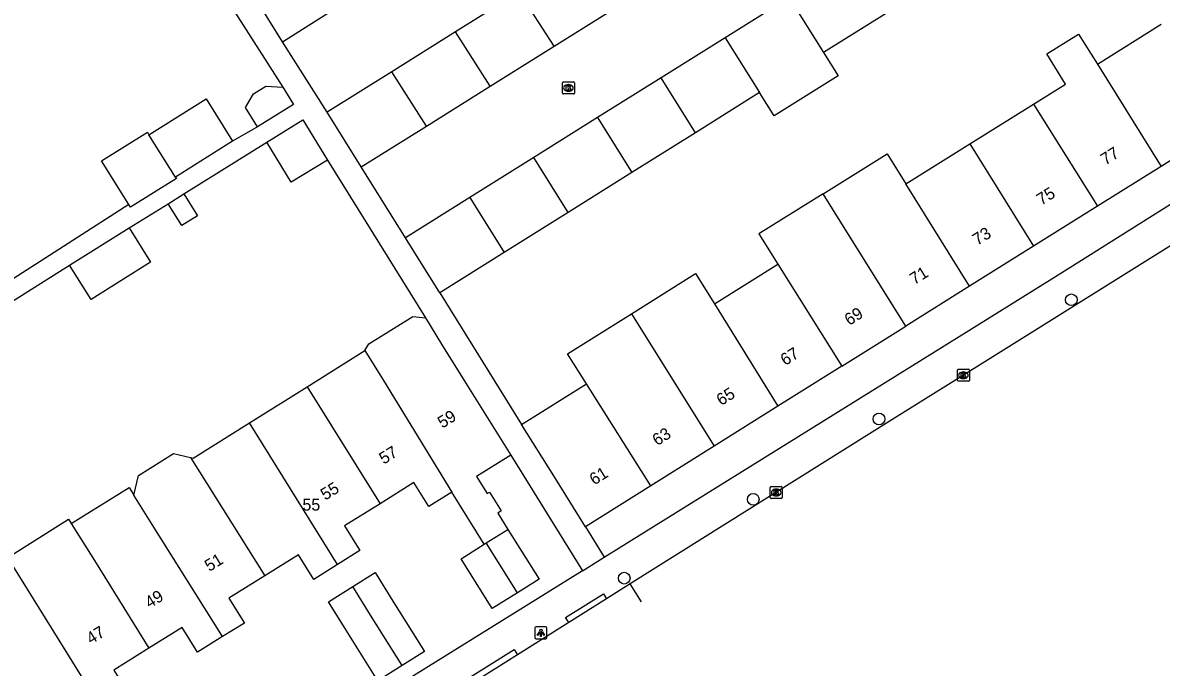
# Model space of a CAD drawing. Extents: x 157767 to 159171, y 387842 to 389425.
# Drawn here: x 158500 to 158595.3, y 387925 to 387978.8 of the extents above; entities that cross this region are included whole.
import ezdxf

# ---------------------------------------------------------------- set-up
doc = ezdxf.new("R2010")
doc.units = 0
for name, color, linetype in [('IMGEO_Boom', 7, 'Continuous'), ('IMGEO_Kolk', 7, 'Continuous'), ('IMGEO_Lichtpunt', 7, 'Continuous'), ('IMGEO_Pand', 7, 'Continuous'), ('IMGEO_Pand_nummerreeks', 7, 'Continuous'), ('IMGEO_Rijbaan_lokaal_gesloten', 7, 'Continuous'), ('IMGEO_Rijbaan_lokaal_open', 7, 'Continuous'), ('IMGEO_Voetpad_open', 7, 'Continuous')]:
    doc.layers.add(name, color=color, linetype=linetype)

msp = doc.modelspace()

# ---------------------------------------------------------------- linework, layer by layer
at = {"layer": 'IMGEO_Boom'}
for centre in [(158587.737, 387955.672), (158571.642, 387945.71), (158561.12, 387938.99), (158550.326, 387932.404)]:
    msp.add_circle(centre, 0.489, dxfattribs=at)
at = {"layer": 'IMGEO_Kolk'}
for p, q in [((158545.159, 387972.955), (158545.159, 387973.807)), ((158545.234, 387973.881), (158546.086, 387973.881)), ((158545.647, 387973.661), (158545.672, 387973.661)), ((158546.16, 387973.807), (158546.16, 387972.955)), ((158546.086, 387972.881), (158545.234, 387972.881)), ((158545.67, 387973.101), (158545.645, 387973.101)), ((158578.205, 387948.94), (158578.205, 387949.792)), ((158578.28, 387949.866), (158579.132, 387949.866)), ((158578.693, 387949.646), (158578.718, 387949.646)), ((158579.206, 387949.792), (158579.206, 387948.94)), ((158579.132, 387948.866), (158578.28, 387948.866)), ((158578.716, 387949.086), (158578.691, 387949.086)), ((158562.544, 387939.138), (158562.544, 387939.99)), ((158562.619, 387940.064), (158563.471, 387940.064)), ((158563.032, 387939.844), (158563.057, 387939.844)), ((158563.545, 387939.99), (158563.545, 387939.138)), ((158563.471, 387939.064), (158562.619, 387939.064)), ((158563.055, 387939.284), (158563.03, 387939.284))]:
    msp.add_line(p, q, dxfattribs=at)
for points in [[(158545.159, 387972.955), (158545.159, 387973.807)], [(158545.234, 387973.881), (158546.086, 387973.881)], [(158545.48, 387973.581), (158545.603, 387973.581), (158545.603, 387973.43), (158545.733, 387973.581), (158545.897, 387973.581), (158545.751, 387973.43), (158545.904, 387973.181), (158545.752, 387973.181), (158545.667, 387973.345), (158545.603, 387973.278), (158545.603, 387973.181), (158545.48, 387973.181), (158545.48, 387973.581)], [(158546.16, 387973.807), (158546.16, 387972.955)], [(158546.086, 387972.881), (158545.234, 387972.881)], [(158578.205, 387948.94), (158578.205, 387949.792)], [(158578.28, 387949.866), (158579.132, 387949.866)], [(158578.526, 387949.566), (158578.649, 387949.566), (158578.649, 387949.415), (158578.779, 387949.566), (158578.943, 387949.566), (158578.797, 387949.415), (158578.95, 387949.166), (158578.798, 387949.166), (158578.713, 387949.33), (158578.649, 387949.263), (158578.649, 387949.166), (158578.526, 387949.166), (158578.526, 387949.566)], [(158579.206, 387949.792), (158579.206, 387948.94)], [(158579.132, 387948.866), (158578.28, 387948.866)], [(158562.544, 387939.138), (158562.544, 387939.99)], [(158562.619, 387940.064), (158563.471, 387940.064)], [(158563.545, 387939.99), (158563.545, 387939.138)], [(158563.471, 387939.064), (158562.619, 387939.064)], [(158562.865, 387939.764), (158562.988, 387939.764), (158562.988, 387939.613), (158563.118, 387939.764), (158563.282, 387939.764), (158563.136, 387939.613), (158563.289, 387939.364), (158563.137, 387939.364), (158563.052, 387939.528), (158562.988, 387939.461), (158562.988, 387939.364), (158562.865, 387939.364), (158562.865, 387939.764)]]:
    msp.add_lwpolyline(points, dxfattribs=at)
for centre, start, end in [((158545.236, 387973.805), 91.55205, 178.44795), ((158545.236, 387973.805), 91.55205, 178.44795), ((158546.084, 387973.805), 1.55205, 88.44795), ((158546.084, 387973.805), 1.55205, 88.44795), ((158545.236, 387972.957), 181.55205, 268.44795), ((158545.236, 387972.957), 181.55205, 268.44795), ((158546.084, 387972.957), 271.55205, 358.44795), ((158546.084, 387972.957), 271.55205, 358.44795), ((158578.282, 387949.79), 91.55205, 178.44795), ((158578.282, 387949.79), 91.55205, 178.44795), ((158579.13, 387949.79), 1.55205, 88.44795), ((158579.13, 387949.79), 1.55205, 88.44795), ((158578.282, 387948.942), 181.55205, 268.44795), ((158578.282, 387948.942), 181.55205, 268.44795), ((158579.13, 387948.942), 271.55205, 358.44795), ((158579.13, 387948.942), 271.55205, 358.44795), ((158562.621, 387939.988), 91.55205, 178.44795), ((158562.621, 387939.988), 91.55205, 178.44795), ((158563.469, 387939.988), 1.55205, 88.44795), ((158563.469, 387939.988), 1.55205, 88.44795), ((158562.621, 387939.14), 181.55205, 268.44795), ((158562.621, 387939.14), 181.55205, 268.44795), ((158563.469, 387939.14), 271.55205, 358.44795), ((158563.469, 387939.14), 271.55205, 358.44795)]:
    msp.add_arc(centre, 0.0765, start, end, dxfattribs=at)
for centre, major_axis, ratio, start_param, end_param in [((158545.646, 387973.381), (-0.387, 0.002), 0.722429, 4.712389, 7.853982), ((158545.671, 387973.381), (-0.39, 0.002), 0.717154, 1.570796, 4.712389), ((158578.692, 387949.366), (-0.387, 0.002), 0.722429, 4.712389, 7.853982), ((158578.717, 387949.366), (-0.39, 0.002), 0.717154, 1.570796, 4.712389), ((158563.031, 387939.564), (-0.387, 0.002), 0.722429, 4.712389, 7.853982), ((158563.056, 387939.564), (-0.39, 0.002), 0.717154, 1.570796, 4.712389)]:
    msp.add_ellipse(centre, major_axis=major_axis, ratio=ratio, start_param=start_param, end_param=end_param, dxfattribs=at)
at = {"layer": 'IMGEO_Lichtpunt'}
for p, q in [((158542.853, 387928.241), (158542.853, 387927.434)), ((158542.853, 387928.241), (158542.853, 387927.434)), ((158543.755, 387928.336), (158542.947, 387928.336)), ((158543.755, 387928.336), (158542.947, 387928.336)), ((158543.849, 387927.434), (158543.849, 387928.241)), ((158543.849, 387927.434), (158543.849, 387928.241)), ((158542.947, 387927.34), (158543.755, 387927.34)), ((158542.947, 387927.34), (158543.755, 387927.34))]:
    msp.add_line(p, q, dxfattribs=at)
for points in [[(158543.227, 387927.905), (158543.266, 387927.877), (158543.078, 387927.615), (158543.04, 387927.642), (158543.227, 387927.905)], [(158543.329, 387927.857), (158543.376, 387927.857), (158543.376, 387927.535), (158543.329, 387927.535), (158543.329, 387927.857)], [(158543.439, 387927.877), (158543.477, 387927.904), (158543.664, 387927.642), (158543.625, 387927.614), (158543.439, 387927.877)]]:
    msp.add_lwpolyline(points, dxfattribs=at)
msp.add_circle((158543.352, 387928.039), 0.0994, dxfattribs=at)
for centre, start, end in [((158542.947, 387928.241), 90, 180), ((158542.947, 387928.241), 90, 180), ((158542.947, 387927.434), 180, 270), ((158542.947, 387927.434), 180, 270), ((158543.755, 387928.241), 0, 90), ((158543.755, 387928.241), 0, 90), ((158543.755, 387927.434), 270, 0), ((158543.755, 387927.434), 270, 360)]:
    msp.add_arc(centre, 0.0946, start, end, dxfattribs=at)
at = {"layer": 'IMGEO_Pand'}
for points in [[(158521.74, 387977.25), (158519.437, 387980.934), (158516.702, 387985.309), (158514.051, 387989.548)], [(158521.74, 387977.25), (158527.213, 387980.683), (158524.909, 387984.355)], [(158541.544, 387981.403), (158536.208, 387978.066)], [(158544.463, 387976.874), (158541.544, 387981.403)], [(158564.131, 387980.929), (158558.764, 387977.574)], [(158564.131, 387980.929), (158567.009, 387976.336)], [(158544.463, 387976.874), (158549.81, 387980.217)], [(158572.341, 387979.67), (158567.009, 387976.336)], [(158536.208, 387978.066), (158530.877, 387974.733)], [(158539.11, 387973.527), (158536.208, 387978.066)], [(158589.921, 387975.378), (158595.269, 387978.721)], [(158558.764, 387977.574), (158553.428, 387974.237)], [(158558.764, 387977.574), (158561.653, 387972.988)], [(158584.581, 387972.039), (158587.251, 387973.708), (158585.68, 387976.221), (158588.347, 387977.888), (158589.921, 387975.378)], [(158539.11, 387973.527), (158544.463, 387976.874)], [(158567.009, 387976.336), (158568.227, 387974.393), (158562.879, 387971.042), (158561.653, 387972.988)], [(158589.921, 387975.378), (158595.252, 387966.827)], [(158530.877, 387974.733), (158525.46, 387971.346)], [(158533.781, 387970.195), (158530.877, 387974.733)], [(158553.428, 387974.237), (158548.092, 387970.901)], [(158556.304, 387969.643), (158553.428, 387974.237)], [(158519.639, 387970.118), (158518.623, 387971.743), (158519.308, 387972.886), (158520.336, 387973.529), (158521.756, 387973.455)], [(158521.756, 387973.455), (158522.661, 387972.008), (158519.639, 387970.118)], [(158533.781, 387970.195), (158539.11, 387973.527)], [(158510.561, 387969.468), (158515.348, 387972.462), (158517.557, 387968.931)], [(158561.653, 387972.988), (158556.304, 387969.643)], [(158528.316, 387966.778), (158525.46, 387971.346)], [(158579.24, 387968.7), (158584.581, 387972.039)], [(158584.581, 387972.039), (158589.925, 387963.497)], [(158520.41, 387968.848), (158523.432, 387970.704), (158525.492, 387967.349)], [(158548.092, 387970.901), (158542.756, 387967.565)], [(158548.092, 387970.901), (158550.965, 387966.305)], [(158508.885, 387963.626), (158506.599, 387967.28), (158510.431, 387969.677), (158510.561, 387969.468)], [(158512.77, 387965.937), (158510.561, 387969.468)], [(158528.316, 387966.778), (158533.781, 387970.195)], [(158556.304, 387969.643), (158550.965, 387966.305)], [(158600.622, 387970.185), (158595.252, 387966.827)], [(158517.557, 387968.931), (158512.77, 387965.937)], [(158525.492, 387967.349), (158522.47, 387965.493), (158520.41, 387968.848)], [(158573.892, 387965.356), (158579.24, 387968.7)], [(158579.24, 387968.7), (158584.573, 387960.151)], [(158542.756, 387967.565), (158537.413, 387964.224)], [(158545.631, 387962.97), (158542.756, 387967.565)], [(158566.966, 387964.537), (158572.316, 387967.879), (158573.892, 387965.356)], [(158595.252, 387966.827), (158589.925, 387963.497)], [(158512.77, 387965.937), (158512.85, 387965.808), (158509.019, 387963.412), (158508.885, 387963.626)], [(158550.965, 387966.305), (158545.631, 387962.97)], [(158579.231, 387956.811), (158573.892, 387965.356)], [(158512.167, 387963.703), (158513.481, 387964.525)], [(158513.481, 387964.525), (158514.626, 387962.694), (158513.312, 387961.872), (158512.167, 387963.703)], [(158537.413, 387964.224), (158532.029, 387960.858)], [(158537.413, 387964.224), (158540.288, 387959.629)], [(158566.966, 387964.537), (158561.603, 387961.184), (158563.181, 387958.659)], [(158573.883, 387953.468), (158568.544, 387962.012), (158566.966, 387964.537)], [(158545.631, 387962.97), (158540.288, 387959.629)], [(158589.925, 387963.497), (158584.573, 387960.151)], [(158503.913, 387958.574), (158508.897, 387961.691)], [(158508.897, 387961.691), (158510.7, 387958.809), (158505.716, 387955.691), (158503.913, 387958.574)], [(158534.902, 387956.262), (158532.029, 387960.858)], [(158584.573, 387960.151), (158579.231, 387956.811)], [(158540.288, 387959.629), (158534.902, 387956.262)], [(158557.871, 387955.339), (158563.181, 387958.659)], [(158563.181, 387958.659), (158568.543, 387950.129)], [(158550.928, 387954.506), (158556.296, 387957.86), (158557.871, 387955.339)], [(158579.231, 387956.811), (158573.883, 387953.468)], [(158557.871, 387955.339), (158563.191, 387946.782)], [(158528.631, 387951.425), (158528.952, 387951.989), (158532.651, 387954.276), (158533.709, 387954.161)], [(158533.709, 387954.161), (158535.046, 387951.961), (158536.933, 387948.93), (158539.576, 387944.686), (158540.827, 387942.677)], [(158547.164, 387948.644), (158545.584, 387951.166), (158550.928, 387954.506)], [(158550.928, 387954.506), (158557.843, 387943.439)], [(158568.543, 387950.129), (158573.883, 387953.468)], [(158523.795, 387948.401), (158528.631, 387951.425)], [(158528.631, 387951.425), (158530.188, 387948.936), (158535.889, 387939.602)], [(158568.543, 387950.129), (158563.191, 387946.782)], [(158518.968, 387945.382), (158523.795, 387948.401)], [(158523.795, 387948.401), (158529.9, 387938.628)], [(158541.735, 387945.25), (158547.164, 387948.644)], [(158552.54, 387940.123), (158547.164, 387948.644)], [(158563.191, 387946.782), (158557.843, 387943.439)], [(158514.045, 387942.492), (158514.265, 387942.441), (158518.968, 387945.382)], [(158526.346, 387933.552), (158518.968, 387945.382)], [(158547.076, 387936.707), (158544.425, 387940.947), (158541.735, 387945.25)], [(158509.3, 387939.336), (158509.679, 387940.983), (158512.619, 387942.822), (158514.045, 387942.492)], [(158540.827, 387942.677), (158537.968, 387940.897), (158538.855, 387939.479), (158539.042, 387939.596), (158540.028, 387938.019), (158539.749, 387937.844), (158540.601, 387936.482)], [(158557.843, 387943.439), (158552.54, 387940.123)], [(158514.045, 387942.492), (158520.248, 387932.586)], [(158504.051, 387936.97), (158508.894, 387939.987), (158509.3, 387939.336)], [(158535.889, 387939.602), (158533.964, 387938.404), (158532.728, 387940.389), (158529.9, 387938.628)], [(158552.54, 387940.123), (158547.076, 387936.707)], [(158516.711, 387927.515), (158510.837, 387936.885), (158509.3, 387939.336)], [(158538.617, 387935.241), (158535.889, 387939.602)], [(158529.9, 387938.628), (158526.923, 387936.773), (158528.207, 387934.711), (158526.346, 387933.552)], [(158506.376, 387921.169), (158506.692, 387921.366), (158504.915, 387924.219), (158500.887, 387930.688), (158498.738, 387934.139), (158503.829, 387937.324), (158504.051, 387936.97)], [(158504.051, 387936.97), (158505.997, 387933.87), (158510.556, 387926.548)], [(158538.779, 387935.343), (158540.601, 387936.482)], [(158540.601, 387936.482), (158543.207, 387932.317), (158541.404, 387931.189)], [(158541.404, 387931.189), (158539.281, 387929.861), (158536.675, 387934.027), (158538.617, 387935.241)], [(158538.617, 387935.241), (158538.779, 387935.343)], [(158541.404, 387931.189), (158538.779, 387935.343)], [(158526.346, 387933.552), (158524.341, 387932.303), (158523.07, 387934.344), (158520.248, 387932.586)], [(158520.248, 387932.586), (158517.255, 387930.722), (158518.542, 387928.655), (158516.711, 387927.515)], [(158527.608, 387931.695), (158529.483, 387932.867), (158530.973, 387930.485), (158533.613, 387926.265), (158531.753, 387925.101)], [(158531.753, 387925.101), (158529.709, 387923.823), (158527.069, 387928.043), (158525.579, 387930.425), (158527.608, 387931.695)], [(158531.753, 387925.101), (158529.098, 387929.312), (158527.608, 387931.695)], [(158516.711, 387927.515), (158514.634, 387926.221), (158513.348, 387928.286), (158510.556, 387926.548)], [(158510.556, 387926.548), (158507.624, 387924.722), (158510.678, 387919.818)]]:
    msp.add_lwpolyline(points, dxfattribs=at)
at = {"layer": 'IMGEO_Rijbaan_lokaal_gesloten'}
for points in [[(158614.047, 387971.463), (158601.914, 387963.875), (158580.957, 387950.772), (158572.725, 387945.625), (158550.833, 387931.916)], [(158551.782, 387930.421), (158551.782, 387930.421), (158550.833, 387931.916)]]:
    msp.add_lwpolyline(points, dxfattribs=at)
at = {"layer": 'IMGEO_Rijbaan_lokaal_open'}
for points in [[(158532.029, 387960.858), (158528.316, 387966.778)], [(158550.833, 387931.916), (158548.849, 387930.674)], [(158548.849, 387930.674), (158545.687, 387928.693)], [(158545.687, 387928.693), (158541.392, 387926.004)], [(158541.392, 387926.004), (158538.456, 387924.165), (158536.303, 387922.827)]]:
    msp.add_lwpolyline(points, dxfattribs=at)
at = {"layer": 'IMGEO_Voetpad_open'}
for points in [[(158512.703, 387987.635), (158521.756, 387973.455)], [(158525.46, 387971.346), (158521.74, 387977.25)], [(158548.655, 387934.165), (158579.393, 387953.259), (158586.637, 387957.759), (158612.576, 387974.073)], [(158519.639, 387970.118), (158517.557, 387968.931)], [(158513.481, 387964.525), (158520.41, 387968.848)], [(158525.492, 387967.349), (158533.709, 387954.161)], [(158508.897, 387961.691), (158512.167, 387963.703)], [(158508.885, 387963.626), (158492.529, 387953.174)], [(158494.254, 387952.481), (158503.913, 387958.574)], [(158534.902, 387956.262), (158541.735, 387945.25)], [(158540.827, 387942.677), (158546.822, 387933.026)], [(158547.076, 387936.707), (158548.655, 387934.165)], [(158546.822, 387933.026), (158548.655, 387934.165)], [(158546.822, 387933.026), (158509.337, 387909.741)], [(158545.687, 387928.693), (158545.425, 387929.118), (158548.587, 387931.099), (158548.849, 387930.674)], [(158536.303, 387922.827), (158536.041, 387923.252), (158541.13, 387926.429), (158541.392, 387926.004)]]:
    msp.add_lwpolyline(points, dxfattribs=at)

# ---------------------------------------------------------------- texts
at = {"layer": 'IMGEO_Pand_nummerreeks'}
for s, rotation, p in [('77', 32.01451, (158590.587, 387966.883)), ('75', 32.01451, (158585.228, 387963.533)), ('73', 32.01451, (158579.87, 387960.183)), ('71', 32.01688, (158574.607, 387956.892)), ('69', 32.01688, (158569.153, 387953.482)), ('67', 32.01451, (158563.794, 387950.132)), ('65', 32.01451, (158558.436, 387946.782)), ('59', 31.56424, (158535.104, 387944.896)), ('63', 32.01451, (158553.077, 387943.431)), ('57', 31.56512, (158530.205, 387941.886)), ('61', 32.01451, (158547.815, 387940.141)), ('55', 31.56512, (158525.306, 387938.877)), ('51', 31.56512, (158515.605, 387932.916)), ('49', 31.56424, (158510.609, 387929.848)), ('47', 31.56424, (158505.71, 387926.838))]:
    msp.add_text(s, height=1, rotation=rotation, dxfattribs=at).set_placement(p)
msp.add_text('55', height=1, dxfattribs=at).set_placement((158523.401, 387938.051))

doc.saveas('drawing.dxf')
